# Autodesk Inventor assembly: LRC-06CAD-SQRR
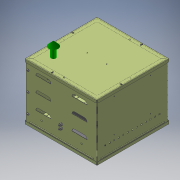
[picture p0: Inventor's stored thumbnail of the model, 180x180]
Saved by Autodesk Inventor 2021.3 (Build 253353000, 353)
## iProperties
description: 0:0:Open Appearance 6" Adjustable - COB LED
manufacturer: 0:0:The Kirlin Company
model: 0:0:LRC-06CAD
url: 0:0:
load_classification: Lighting
motor: 0 ul
Part Number: LRC-06CAD-SQRR
Document SubType Name: Assembly
Designer: JChurch
Author: JChurch
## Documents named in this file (7)
- X:\Revit Files\0000-Un-Zipped\COB\LRC-06CAD-SQR\LRC-06CAD-SQRR.iam
- X:\INVENTOR\830\830376-00-00.iam
- X:\INVENTOR\881\881035-00-00.iam
- X:\INVENTOR\830\830402-00-00.ipt
- X:\INVENTOR\KIRLIN_ENG\750\750055-00-XX.iam
- X:\INVENTOR\725\725267-00-00.ipt
- X:\Revit Files\0000-Un-Zipped\COB\LRC-06CAD-SQR\LRC-06CAD-SQRR_Substitute_1.ipt
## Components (6 placed, 6 different names)
1. 830376-00-00:1 [sub-assembly] — Mate:1, Mate:2, Flush:1, Mate:3, Angle:1, Mate:7
2. 881035-00-00:1 [sub-assembly] — Mate:3, Mate:4, Angle:1, Mate:5, Angle:2
3. 830402-00-00:1 — Mate:5, Mate:6, Angle:2
4. 750055-00-XX:1 [sub-assembly] — Mate:7, Mate:8, Mate:9, Mate:10, Mate:11, Mate:12
5. 725267-00-00:1 — Mate:10, Mate:11, Mate:12
6. LRC-06CAD-SQRR_Substitute_1:1
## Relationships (15: Mate 12, Angle 2, Flush 1)
- Mate:1: 830376-00-00:1
- Mate:2: 830376-00-00:1
- Flush:1: 830376-00-00:1
- Mate:3: 830376-00-00:1 ↔ 881035-00-00:1
- Mate:4: 881035-00-00:1
- Angle:1: 830376-00-00:1 ↔ 881035-00-00:1
- Mate:5: 881035-00-00:1 ↔ 830402-00-00:1
- Mate:6: 830402-00-00:1
- Angle:2: 881035-00-00:1 ↔ 830402-00-00:1
- Mate:7: 830376-00-00:1 ↔ 750055-00-XX:1
- Mate:8: 750055-00-XX:1
- Mate:9: 750055-00-XX:1
- Mate:10: 750055-00-XX:1 ↔ 725267-00-00:1
- Mate:11: 750055-00-XX:1 ↔ 725267-00-00:1
- Mate:12: 750055-00-XX:1 ↔ 725267-00-00:1
